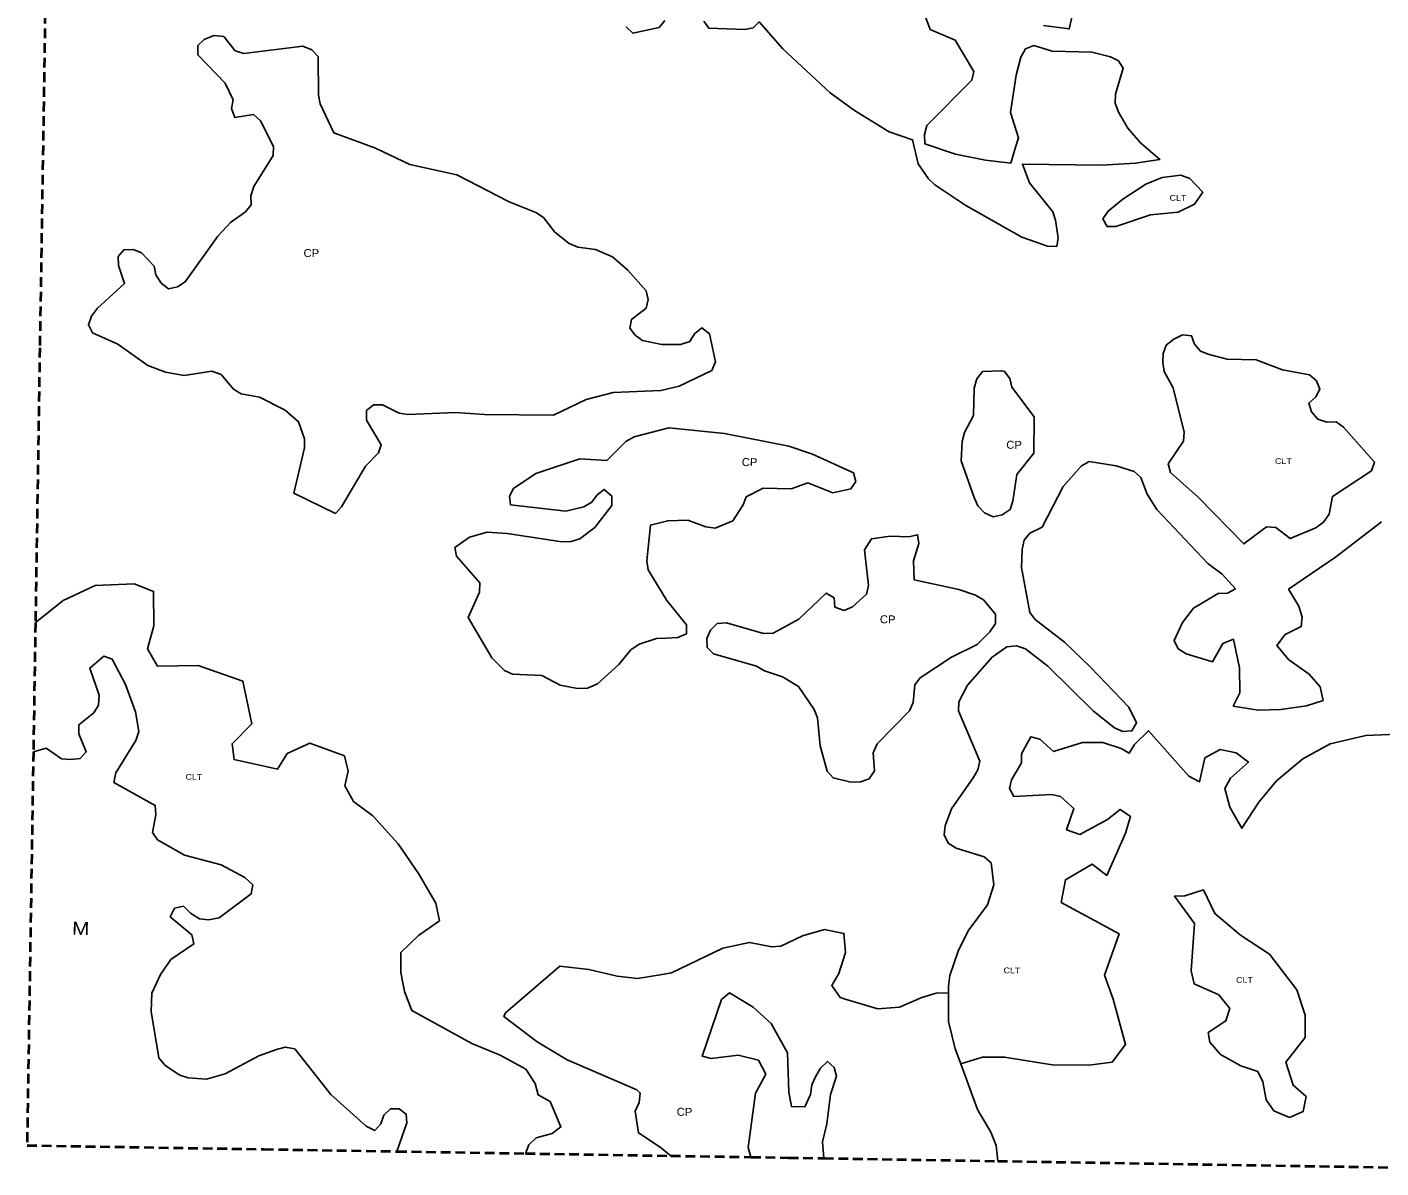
# Model space of a CAD drawing. Extents: x 713589 to 726391, y 7177764 to 7191819.
# Drawn here: x 713589 to 714671, y 7177953 to 7178865 of the extents above; entities that cross this region are included whole.
import ezdxf
from ezdxf.enums import TextEntityAlignment as Align

# ---------------------------------------------------------------- set-up
doc = ezdxf.new("R2010")
doc.units = 0
doc.header["$LTSCALE"] = 2.6
doc.linetypes.add('MEDIUM_DASHED', pattern=[4.5, 3, -1.5])
doc.layers.add('63', color=7, linetype='Continuous', lineweight=25)

msp = doc.modelspace()

# ---------------------------------------------------------------- linework, layer by layer
at = {"layer": '63', "linetype": 'MEDIUM_DASHED', "lineweight": 40}
for p, q in [((713595.68, 7178388.53), (713594.03, 7178285.29)), ((713884.72, 7177965.87), (713987.36, 7177964.22)), ((713987.36, 7177964.22), (714103.74, 7177962.34)), ((714103.74, 7177962.34), (714167.71, 7177961.31))]:
    msp.add_line(p, q, dxfattribs=at)
for points in [[(713604, 7178910.37), (713599.18, 7178608.3), (713595.68, 7178388.53)], [(713594.03, 7178285.29), (713589.01, 7177970.64), (713778.2, 7177967.59), (713884.72, 7177965.87)], [(714167.71, 7177961.31), (714197.82, 7177960.82), (714225.91, 7177960.37)], [(714225.91, 7177960.37), (714365.01, 7177958.13), (714704.43, 7177952.65)]]:
    msp.add_lwpolyline(points, dxfattribs=at)
at = {"layer": '63'}
for points in [[(714306.04, 7178876.31), (714311.1, 7178862.72), (714331.08, 7178854.18), (714345.84, 7178829.19), (714344.28, 7178822.12), (714308.43, 7178785.84), (714306.43, 7178778.66), (714306.64, 7178771.33), (714331.26, 7178762.97), (714355.12, 7178758.29), (714375.44, 7178755.97), (714379.34, 7178768.52), (714381.66, 7178775.99), (714375.28, 7178796.44), (714379.64, 7178826.26), (714383.53, 7178840.5), (714387.3, 7178847.13), (714393.93, 7178849.99), (714408.51, 7178845.32), (714440.21, 7178844.5), (714455.12, 7178840.83), (714461.52, 7178837.61), (714465.38, 7178831.75), (714459.05, 7178811.1)], [(714424.68, 7178874.79), (714422.19, 7178863.19), (714401.58, 7178865.9)], [(714098.79, 7178869.81), (714094.25, 7178864.18), (714073.25, 7178859.69), (714068.07, 7178864.78)], [(714459.05, 7178811.1), (714458.92, 7178803.7), (714461.56, 7178796.63), (714469.16, 7178783.8), (714479.2, 7178772.07), (714494.66, 7178758.66), (714475.08, 7178755.78), (714447.9, 7178754.16), (714384.72, 7178754.93), (714390.55, 7178740.19), (714408.96, 7178716.85), (714411.27, 7178710.21), (714413.45, 7178696.18), (714412.22, 7178689.22), (714404.93, 7178689.57), (714384.29, 7178696.78), (714339.48, 7178721.93), (714314.87, 7178738.43), (714309.58, 7178743.3), (714301.31, 7178755.36), (714296.94, 7178774.62), (714278.27, 7178780.96), (714250.45, 7178797.91), (714230.93, 7178812.19), (714193.2, 7178847.38), (714174.26, 7178868.83), (714169.59, 7178864.17), (714162.74, 7178862.63), (714134.02, 7178863.67), (714129.94, 7178869.43)], [(713760.28, 7178571.43), (713753.99, 7178575.09), (713744.07, 7178587.03), (713736.78, 7178589.7), (713714.57, 7178586.09), (713699.66, 7178588.76), (713685.42, 7178594.09), (713661.59, 7178611.03), (713641.39, 7178620.35), (713638.08, 7178626.65), (713640.42, 7178633.6), (713645.4, 7178639.89), (713666.97, 7178659.74), (713662.02, 7178674), (713661.71, 7178681.29), (713666.35, 7178686.59), (713673.98, 7178686.91), (713680.6, 7178684.24), (713690.53, 7178673.62), (713691.84, 7178666.66), (713696.14, 7178660.02), (713702.09, 7178655.37), (713709.39, 7178657.02), (713715.36, 7178660.99), (713741.6, 7178697.4), (713751.56, 7178708.32), (713763.51, 7178716.92), (713768.16, 7178722.54), (713767.84, 7178729.83), (713770.17, 7178737.12), (713785.79, 7178761.95), (713786.13, 7178769.24), (713775.56, 7178789.81), (713769.93, 7178794.79), (713755.02, 7178792.49), (713752.38, 7178799.46), (713753.71, 7178806.41), (713747.44, 7178819.68), (713725.6, 7178842.58), (713725.62, 7178849.87), (713730.6, 7178854.84), (713738.22, 7178857.81), (713746.18, 7178857.13), (713755.44, 7178845.52), (713762.39, 7178843.52), (713809.46, 7178849.4), (713816.75, 7178846.41), (713821.71, 7178841.1), (713821.99, 7178810.28), (713823.31, 7178803.31), (713834.24, 7178780.17), (713867.66, 7178767.78), (713895.14, 7178754.81), (713932.58, 7178746.46), (713974.3, 7178724.85), (713995.83, 7178716.53), (714001.79, 7178712.54), (714011.05, 7178700.6), (714022.3, 7178691.63), (714029.25, 7178688.64), (714043.5, 7178686.96), (714057.08, 7178680.97), (714069.32, 7178670.34), (714083.88, 7178653.75), (714085.52, 7178646.78), (714083.86, 7178639.83), (714072.24, 7178630.9), (714070.9, 7178623.94), (714075.2, 7178618.3), (714081.16, 7178613.98), (714096.4, 7178610.97), (714111.32, 7178610.95), (714118.94, 7178613.26), (714122.6, 7178619.55), (714128.57, 7178624.18), (714134.53, 7178619.53), (714139.46, 7178596.98), (714136.47, 7178590.03), (714110.27, 7178577.48), (714095.68, 7178574.19), (714057.56, 7178572.59), (714036.01, 7178567), (714009.81, 7178554.45), (713954.8, 7178554.87), (713931.6, 7178556.56), (713893.48, 7178554.97), (713886.53, 7178555.98), (713873.28, 7178562.63), (713865.99, 7178562.64), (713860.35, 7178558.01), (713860.34, 7178550.39), (713872.23, 7178530.81), (713869.9, 7178524.19), (713859.61, 7178513.6), (713840.34, 7178481.15)], [(713840.34, 7178481.15), (713835.69, 7178475.86), (713802.24, 7178492.15), (713810.92, 7178528.26), (713810.93, 7178535.55), (713805.98, 7178549.15), (713795.39, 7178558.45), (713774.86, 7178568.76), (713760.28, 7178571.43)], [(714671.72, 7178469.07), (714635.13, 7178440.78), (714597.55, 7178415.41), (714605.77, 7178401.67), (714608.4, 7178393.05), (714607.73, 7178385.43), (714594.79, 7178379.15), (714588.15, 7178370.22), (714597.74, 7178358.93), (714613.96, 7178347.31), (714622.89, 7178337.35), (714625.2, 7178326.41), (714611.93, 7178322.12), (714591.38, 7178319.17), (714573.15, 7178318.54), (714553.27, 7178321.89), (714558.59, 7178332.48), (714558.29, 7178352.37), (714553.57, 7178375.13), (714553.53, 7178375.31), (714545.01, 7178371.92), (714536.66, 7178357.1), (714515.56, 7178363.71), (714509.27, 7178367.7), (714505.97, 7178374.33), (714512.62, 7178388.57), (714521.59, 7178400.15), (714541.16, 7178411.72), (714548.78, 7178412.04), (714555.08, 7178415.67), (714544.5, 7178427.29), (714532.91, 7178435.93), (714492.22, 7178479.08), (714484.62, 7178491.35), (714479.34, 7178504.62), (714474.04, 7178509.27), (714459.8, 7178513.93), (714438.26, 7178517.28), (714431.96, 7178513.98), (714417.35, 7178497.43), (714400.47, 7178464.85), (714390.78, 7178460.03), (714386.13, 7178454.4), (714384.46, 7178447.11), (714384.1, 7178432.53), (714390.67, 7178396.73), (714394.97, 7178391.08), (714418.47, 7178372.82), (714439.32, 7178352.9), (714469.75, 7178321.03), (714476.03, 7178308.43), (714472.37, 7178302.14), (714465.08, 7178301.49), (714458.46, 7178304.48), (714441.58, 7178317.77), (714405.18, 7178353.62), (714387.31, 7178367.57), (714380.02, 7178369.9), (714372.4, 7178369.25), (714360.45, 7178360.98), (714340.86, 7178338.48), (714333.88, 7178325.23), (714333.54, 7178317.94), (714350.71, 7178277.81), (714349.04, 7178270.86), (714345.38, 7178264.57), (714328.11, 7178239.74), (714323.11, 7178226.16), (714322.11, 7178218.87), (714325.41, 7178212.24), (714331.7, 7178208.25), (714354.22, 7178201.25), (714359.84, 7178196.51), (714361.94, 7178178.92), (714356.95, 7178162.9), (714341.5, 7178142.22), (714333.52, 7178126), (714326.86, 7178106.45), (714325.68, 7178097.96), (714325.7, 7178092.61)], [(713595.68, 7178388.53), (713600.89, 7178392.71), (713600.91, 7178392.73), (713617.83, 7178406.29), (713643.37, 7178418.18), (713674.53, 7178419.45), (713690.09, 7178413.46), (713690.38, 7178385.96), (713685.38, 7178367.74), (713693.31, 7178353.8), (713725.78, 7178354.36), (713761.56, 7178341.76), (713768.8, 7178307.61), (713752.86, 7178291.73), (713754.5, 7178279.13), (713789.28, 7178271.45), (713796.93, 7178284.04), (713815.17, 7178292.29), (713842.66, 7178281.97), (713845.62, 7178269.7), (713842.95, 7178258.11), (713849.89, 7178245.5), (713865.45, 7178234.21), (713885.62, 7178211.64), (713901.82, 7178188.08), (713915.7, 7178164.2), (713918.66, 7178150.27), (713902.07, 7178138.37), (713887.8, 7178124.81), (713887.77, 7178108.9), (713890.73, 7178093.65), (713896.67, 7178078.39), (713944.68, 7178052.13), (713967.2, 7178042.82), (713987.73, 7178031.51), (713995.34, 7178020.23), (713997.64, 7178010.95), (714007.24, 7178005.63), (714015.83, 7177985.4), (714008.8, 7177980.24), (713995.92, 7177976.72), (713990.1, 7177971.23), (713987.36, 7177964.22)], [(713884.72, 7177965.87), (713892.56, 7177988.58), (713892.12, 7177995.69), (713886.47, 7177999.88), (713879.47, 7178000.01), (713874.17, 7177994.73), (713871.82, 7177987.82), (713866.94, 7177982.54), (713859.98, 7177985.94), (713831.98, 7178011.38), (713803.05, 7178047.72), (713795.46, 7178049.22), (713788.31, 7178047.41), (713774.37, 7178042.2), (713747.46, 7178027.89), (713732.52, 7178023.62), (713717.88, 7178024.73), (713711.13, 7178026.92), (713699.36, 7178034.62), (713694.28, 7178040.71), (713688.26, 7178077.65), (713688.78, 7178092.35), (713695.79, 7178107.38), (713704.07, 7178119.15), (713722.35, 7178131.75), (713720.64, 7178139.06), (713703.32, 7178153.38), (713706.93, 7178160.18), (713714.19, 7178161.89), (713719.63, 7178156.22), (713726.81, 7178151.77), (713734.02, 7178151.01), (713742.5, 7178152.46), (713768.23, 7178171.72), (713769.47, 7178179.04), (713763.13, 7178184.81), (713744.19, 7178194.85), (713714.78, 7178202.76), (713693.31, 7178214.95), (713689.18, 7178220.83), (713691.82, 7178234.85), (713691.42, 7178242.43), (713658.5, 7178260.85), (713659.89, 7178268.55), (713676.08, 7178294.25), (713678.42, 7178301.58), (713675.63, 7178317.31), (713667.65, 7178339.08), (713657.05, 7178359.22), (713650.36, 7178361.72), (713639.17, 7178352.25), (713646.62, 7178330.53), (713646.12, 7178322.68), (713642.25, 7178316.46), (713630.48, 7178306.73), (713630.4, 7178299.62), (713636.3, 7178285.26), (713631.42, 7178280.03), (713623.63, 7178279.27), (713616.57, 7178279.56), (713604.22, 7178288.15), (713594.03, 7178285.29)], [(714335.5, 7178035.95), (714352.9, 7178041.31), (714370.46, 7178041.29), (714408.56, 7178034.93), (714437.73, 7178034.88), (714456.62, 7178037.17), (714467.25, 7178051.4), (714457.37, 7178087.54), (714450.44, 7178106.77), (714462.1, 7178139.89), (714415.74, 7178164.83), (714419.08, 7178183.05), (714440.43, 7178195.5), (714452.17, 7178186.45), (714467.27, 7178220.29), (714471.27, 7178233.54), (714462.99, 7178239.18), (714452.7, 7178231.25), (714430.73, 7178219.17), (714420.07, 7178223.02), (714425.99, 7178239.91), (714425.79, 7178240.09), (714415.22, 7178249.6), (714408.26, 7178251.27), (714377.77, 7178249.67), (714374.46, 7178255.97), (714376.13, 7178262.92), (714384.11, 7178276.5), (714384.12, 7178283.79), (714391.43, 7178297.37), (714398.72, 7178295.37), (714409.64, 7178285.41), (714432.85, 7178292.66), (714449.09, 7178292.63), (714463.67, 7178287.97), (714470.13, 7178284.24), (714474.28, 7178291.22), (714485.44, 7178302.15), (714485.76, 7178301.8), (714517.72, 7178265.94), (714526.33, 7178261.28), (714530.67, 7178280.5), (714542.94, 7178287.11), (714555.53, 7178284.43), (714565.46, 7178277.13), (714551.19, 7178264.23), (714546.53, 7178255.95), (714550.49, 7178241.03), (714560.22, 7178224.2), (714573.66, 7178244.91), (714587.94, 7178262.12), (714608.85, 7178279.65), (714630.74, 7178291.54), (714659.25, 7178298.45), (714684.44, 7178299.41)], [(714325.7, 7178092.61), (714315.93, 7178092.28), (714304.33, 7178088.99), (714286.42, 7178081.06), (714269.18, 7178079.77), (714243.13, 7178087.54), (714239.04, 7178088.76), (714232.43, 7178098.39), (714238.08, 7178107.99), (714243.41, 7178124.88), (714242.11, 7178140.13), (714226.53, 7178143.14), (714208.96, 7178138.19), (714191.71, 7178129.94), (714184.42, 7178129.29), (714166.53, 7178132.96), (714145.31, 7178128.36), (714104.19, 7178108.54), (714096.78, 7178107.29), (714077, 7178103.95), (714060.77, 7178105.96), (714038.24, 7178111.3), (714015.04, 7178113.99), (713971.57, 7178076.61), (713970.24, 7178073.63), (713996.72, 7178053.37), (714020.89, 7178039.08), (714076.52, 7178015.13), (714079.17, 7178012.47), (714078.49, 7178004.85), (714075.17, 7177997.9), (714077.79, 7177980.66), (714095.1, 7177969.24), (714103.74, 7177962.34)], [(714225.91, 7177960.37), (714224.86, 7177973.52), (714228.53, 7177987.77), (714231.22, 7178011.29), (714236.22, 7178025.87), (714234.24, 7178032.83), (714228.94, 7178037.81), (714223.3, 7178032.52), (714219.31, 7178025.56), (714216.32, 7178018.94), (714215.31, 7178011.32), (714210.89, 7178001.36), (714200.53, 7178001.74), (714200.08, 7178001.76), (714198.15, 7178013.27), (714196.88, 7178044.76), (714183.99, 7178067.98), (714169.43, 7178081.26), (714150.56, 7178092.56), (714144.25, 7178087.26), (714128.6, 7178041.89), (714135.89, 7178040.22), (714157.43, 7178042.83), (714173.67, 7178038.83), (714179.61, 7178027.55), (714171.3, 7178012.32), (714165.6, 7177968.91), (714167.71, 7177961.31)], [(714325.7, 7178092.61), (714325.8, 7178069.67), (714331.12, 7178047.92), (714335.5, 7178035.95)], [(714335.5, 7178035.95), (714348.89, 7177999.37), (714359.46, 7177981.13), (714363.75, 7177970.51), (714365.01, 7177958.13)]]:
    msp.add_lwpolyline(points, dxfattribs=at)
for points in [[(714449.16, 7178711.48), (714452.46, 7178705.17), (714459.53, 7178705.16), (714487.28, 7178714.62), (714509.15, 7178716.79), (714522.31, 7178722.95), (714528.89, 7178732.73), (714518.48, 7178743.51), (714511.3, 7178746.39), (714496.61, 7178744.32), (714483.34, 7178739.04), (714464.98, 7178727.03), (714453.26, 7178717.43)], [(714614.36, 7178586.59), (714619.98, 7178581.94), (714622.63, 7178575.3), (714619.3, 7178569.01), (714613.66, 7178564.05), (714615.97, 7178557.09), (714620.93, 7178551.11), (714628.22, 7178548.78), (714635.51, 7178549.1), (714641.47, 7178544.78), (714666.27, 7178516.9), (714663.94, 7178509.95), (714632.76, 7178489.45), (714630.08, 7178475.2), (714625.43, 7178468.92), (714619.46, 7178464.29), (714598.9, 7178455.7), (714587.31, 7178464.67), (714580.02, 7178465.01), (714561.71, 7178451.49), (714525.38, 7178488.97), (714503.21, 7178508.56), (714501.23, 7178515.52), (714513.52, 7178533.73), (714514.2, 7178540.69), (714505.31, 7178576.16), (714498.04, 7178589.43), (714497.05, 7178596.39), (714497.4, 7178603.68), (714499.73, 7178610.31), (714505.7, 7178615.27), (714512.67, 7178618.57), (714519.96, 7178617.89), (714522.27, 7178611.26), (714527.23, 7178605.62), (714534.18, 7178602.96), (714548.43, 7178599.29), (714571.63, 7178598.59), (714592.82, 7178590.6)], [(714354.35, 7178476.32), (714349.06, 7178481.97), (714346.08, 7178488.6), (714335.86, 7178517.78), (714336.55, 7178533.36), (714338.55, 7178540.64), (714345.53, 7178554.22), (714346.23, 7178576.09), (714348.23, 7178583.38), (714352.88, 7178589.34), (714367.86, 7178589.9), (714370.44, 7178589.31), (714374.74, 7178583.67), (714376.39, 7178576.71), (714394.25, 7178553.15), (714393.87, 7178523.98), (714380.25, 7178507.1), (714377.23, 7178485.57), (714374.9, 7178478.94), (714368.6, 7178474.64), (714361.3, 7178473)], [(713977.9, 7178495.84), (713974.57, 7178489.55), (713975.55, 7178482.59), (714019.62, 7178477.54), (714034.21, 7178481.16), (714040.52, 7178484.8), (714044.83, 7178490.76), (714050.47, 7178495.06), (714056.43, 7178489.74), (714056.42, 7178482.12), (714042.8, 7178464.58), (714030.86, 7178455.65), (714023.89, 7178453.34), (714016.6, 7178453.02), (713972.87, 7178459.72), (713956.96, 7178460.74), (713942.7, 7178456.79), (713931.09, 7178448.52), (713932.4, 7178441.56), (713950.93, 7178420.32), (713950.58, 7178413.03), (713941.66, 7178392.74), (713960.57, 7178360.53), (713970.66, 7178350.3), (713977.15, 7178347.43), (714000.43, 7178346.3), (714015.2, 7178338.61), (714029.16, 7178335.97), (714037.12, 7178336.26), (714044.95, 7178339.5), (714062.06, 7178355.2), (714071.71, 7178366.92), (714078.38, 7178371.21), (714092.2, 7178375.83), (714100.06, 7178376.14), (714109.27, 7178376.64), (714116.23, 7178379.62), (714116.25, 7178386.91), (714100.43, 7178406.2), (714085.5, 7178430.7), (714084.52, 7178438), (714087.55, 7178466.49), (714101.21, 7178469.99), (714117.38, 7178470.42), (714131.62, 7178465.09), (714139.24, 7178464.09), (714153.17, 7178470.03), (714161.48, 7178482.61), (714163.81, 7178489.23), (714177.41, 7178496.17), (714199.94, 7178495.47), (714213.21, 7178500.42), (714233.08, 7178492.43), (714247.67, 7178495.39), (714251.65, 7178501.35), (714249.68, 7178508.31), (714216.89, 7178523.28), (714198.01, 7178529.61), (714146.66, 7178539.64), (714102.11, 7178544.21), (714074.41, 7178537.11), (714067.77, 7178533.47), (714052.5, 7178518.25), (714030.96, 7178519.61), (713995.81, 7178507.74)], [(714228.73, 7178269.73), (714223.13, 7178289.96), (714220.85, 7178312.5), (714218.21, 7178319.13), (714205.65, 7178337.38), (714193.07, 7178345.35), (714178.49, 7178350.02), (714172.2, 7178353.67), (714137.75, 7178363.67), (714132.79, 7178368.65), (714132.47, 7178375.94), (714135.46, 7178382.57), (714140.77, 7178387.86), (714148.06, 7178388.51), (714177.88, 7178379.84), (714185.5, 7178380.16), (714206.07, 7178391.4), (714227.97, 7178412.24), (714234.26, 7178408.25), (714234.92, 7178400.96), (714242.2, 7178398.3), (714248.84, 7178401.27), (714260.12, 7178411.19), (714261.79, 7178418.15), (714258.52, 7178446.66), (714264.06, 7178455.43), (714279.09, 7178457.56), (714294, 7178457.2), (714300.96, 7178458.85), (714301.95, 7178451.89), (714297.61, 7178437.97), (714298.25, 7178422.73), (714334.03, 7178415.05), (714347.28, 7178410.39), (714353.57, 7178406.73), (714363.16, 7178395.45), (714363.15, 7178387.82), (714358.83, 7178381.2), (714348.54, 7178370.95), (714327.98, 7178361.04), (714303.09, 7178344.51), (714298.77, 7178338.88), (714297.43, 7178324.63), (714294.43, 7178318.01), (714268.54, 7178291.54), (714265.54, 7178284.58), (714266.51, 7178270), (714262.2, 7178263.71), (714255.23, 7178261.4), (714247.61, 7178261.08), (714233.36, 7178264.42)], [(714598.39, 7177992.85), (714609.34, 7177997.81), (714611.68, 7178009.73), (714601.09, 7178018.7), (714595.48, 7178037.27), (714610.76, 7178056.79), (714610.79, 7178074.69), (714604.2, 7178094.92), (714582.37, 7178123.46), (714559.2, 7178138.74), (714538.68, 7178156.01), (714529.43, 7178174.86), (714514.54, 7178170.11), (714506.26, 7178169.87), (714522.43, 7178148.08), (714519.71, 7178110.3), (714522.01, 7178099.69), (714541.89, 7178091.04), (714550.48, 7178080.09), (714547.48, 7178070.16), (714533.22, 7178060.9), (714534.53, 7178053.28), (714543.13, 7178043.32), (714559.36, 7178034.34), (714572.94, 7178029.68), (714576.9, 7178021.39), (714579.53, 7178007.13), (714585.81, 7177998.18)]]:
    msp.add_lwpolyline(points, close=True, dxfattribs=at)

# ---------------------------------------------------------------- texts
for s, height, width, p in [('CLT', 4.64, 1.15, (714509.08, 7178725.73)), ('CP', 6.4, 1.05, (713816.22, 7178680.74)), ('CP', 6.4, 1.05, (714378.05, 7178527.5)), ('CP', 6.4, 1.05, (714166.6, 7178513.66)), ('CLT', 4.64, 1.15, (714593.4, 7178515.34)), ('CP', 6.4, 1.05, (714276.99, 7178387.99)), ('CLT', 4.64, 1.15, (713722.33, 7178262.92)), ('M', 10.4, 1.2, (713631.87, 7178138.91)), ('CLT', 4.64, 1.15, (714376.32, 7178108.17)), ('CLT', 4.64, 1.15, (714562.25, 7178100.62)), ('CP', 6.4, 1.05, (714114.57, 7177994.26)), ('M', 0.52, 1.2, (714215.49, 7177975.96))]:
    msp.add_text(s, height=height, rotation=359.062, dxfattribs=dict(at, width=width)).set_placement(p, align=Align.CENTER)

doc.saveas('drawing.dxf')
